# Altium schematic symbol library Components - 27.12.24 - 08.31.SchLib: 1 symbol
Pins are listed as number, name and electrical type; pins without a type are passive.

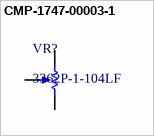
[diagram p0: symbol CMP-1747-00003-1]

## CMP-1747-00003-1
designator VR?, comment 3362P-1-104LF
Square Trimpot(R) Trimming Potentiometer, 100 KOhm, 300 V, -55 to 125 degC, 3-Pin THD, RoHS, Tube; Voltage Rating: 250 V; Case\Package: Axial; Tolerance: 1%; Power Rating: 250 mW; Resistance: 1 mohm
footprint BOUR-3362P (THD, 3-Leads, Body 6.6x6.99mm, Pitch 2.54mm)
pins: 1 CCW, 2 S, 3 CW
